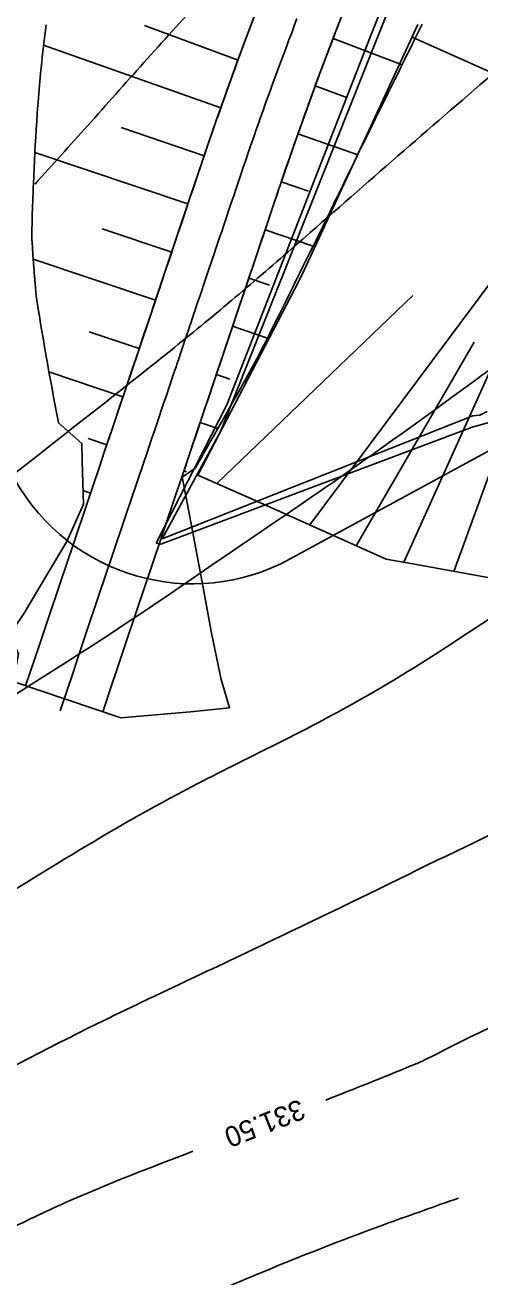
# Model space of a CAD drawing. Extents: x -564037 to -563827, y -1163561 to -1163412.
# Drawn here: x -563903.66 to -563892.49, y -1163523.9 to -1163493.12 of the extents above; entities that cross this region are included whole.
import ezdxf

# ---------------------------------------------------------------- set-up
doc = ezdxf.new("R2010")
doc.units = 0
for name, color, linetype in [('5', 7, 'Continuous'), ('Default', 7, 'Continuous'), ('Line', 7, 'Continuous'), ('Vrstva 24', 7, 'Continuous'), ('Vrstva 25', 7, 'Continuous'), ('Vrstva 26', 7, 'Continuous')]:
    doc.layers.add(name, color=color, linetype=linetype)

msp = doc.modelspace()

# ---------------------------------------------------------------- linework, layer by layer
for p, q in [((-563890.151, -1163481.173), (-563898.85, -1163503.099)), ((-563898.85, -1163503.099), (-563900.295, -1163505.749))]:
    msp.add_line(p, q)
msp.add_lwpolyline([(-563900.324, -1163505.882), (-563892.678, -1163503.006), (-563888.735, -1163501.906), (-563886.271, -1163502.018), (-563883.536, -1163500.684), (-563878.095, -1163497.234), (-563876.621, -1163489.849), (-563880.163, -1163485.998), (-563881.977, -1163484.515), (-563883.765, -1163483.269), (-563890.133, -1163481.092), (-563891.974, -1163485.382), (-563895.143, -1163493.304), (-563898.704, -1163502.458), (-563900.439, -1163505.855)], close=True)
for points in [[(-563901.709, -1163503.594), (-563901.519, -1163503.03), (-563901.312, -1163502.416), (-563901.2, -1163502.083), (-563900.88, -1163501.135), (-563900.561, -1163500.187), (-563900.242, -1163499.24), (-563899.923, -1163498.292), (-563899.604, -1163497.344), (-563899.329, -1163496.528), (-563899.284, -1163496.395), (-563898.956, -1163495.44), (-563898.618, -1163494.488), (-563898.566, -1163494.344), (-563898.27, -1163493.54), (-563897.913, -1163492.595)], [(-563899.813, -1163504.233), (-563899.623, -1163503.669), (-563899.417, -1163503.055), (-563899.304, -1163502.721), (-563898.985, -1163501.773), (-563898.666, -1163500.826), (-563898.347, -1163499.878), (-563898.027, -1163498.93), (-563897.708, -1163497.982), (-563897.433, -1163497.166), (-563897.39, -1163497.036), (-563897.068, -1163496.1), (-563896.736, -1163495.167), (-563896.685, -1163495.026), (-563896.396, -1163494.237), (-563896.046, -1163493.311), (-563895.888, -1163492.903)], [(-563903.651, -1163509.364), (-563903.434, -1163508.717), (-563903.304, -1163508.333), (-563903.114, -1163507.769), (-563902.795, -1163506.821), (-563902.476, -1163505.873), (-563902.157, -1163504.926), (-563901.838, -1163503.978), (-563901.709, -1163503.594), (-563901.613, -1163503.31), (-563901.612, -1163503.306), (-563901.552, -1163503.131), (-563901.519, -1163503.03), (-563901.493, -1163502.955), (-563901.434, -1163502.78), (-563901.375, -1163502.605), (-563901.316, -1163502.429), (-563901.257, -1163502.254), (-563901.2, -1163502.083), (-563901.198, -1163502.079), (-563901.139, -1163501.904), (-563901.08, -1163501.728), (-563901.021, -1163501.553), (-563900.962, -1163501.378), (-563900.903, -1163501.202), (-563900.88, -1163501.135), (-563900.844, -1163501.027), (-563900.785, -1163500.852), (-563900.726, -1163500.676), (-563900.667, -1163500.501), (-563900.608, -1163500.326), (-563900.561, -1163500.187), (-563900.549, -1163500.15), (-563900.49, -1163499.975), (-563900.431, -1163499.8), (-563900.372, -1163499.624), (-563900.313, -1163499.449), (-563900.254, -1163499.274), (-563900.242, -1163499.24), (-563900.194, -1163499.098), (-563900.135, -1163498.923), (-563900.076, -1163498.748), (-563900.017, -1163498.572), (-563899.958, -1163498.397), (-563899.923, -1163498.292), (-563899.899, -1163498.222), (-563899.84, -1163498.046), (-563899.781, -1163497.871), (-563899.722, -1163497.696), (-563899.663, -1163497.52), (-563899.604, -1163497.345), (-563899.604, -1163497.344), (-563899.545, -1163497.17), (-563899.486, -1163496.994), (-563899.427, -1163496.819), (-563899.368, -1163496.644), (-563899.329, -1163496.528), (-563899.309, -1163496.468), (-563899.284, -1163496.395), (-563899.249, -1163496.291), (-563899.188, -1163496.114), (-563899.128, -1163495.937), (-563899.067, -1163495.761), (-563899.006, -1163495.584), (-563898.956, -1163495.44), (-563898.944, -1163495.408), (-563898.882, -1163495.231), (-563898.82, -1163495.055), (-563898.758, -1163494.879), (-563898.695, -1163494.703), (-563898.632, -1163494.527), (-563898.618, -1163494.488), (-563898.568, -1163494.351), (-563898.566, -1163494.344), (-563898.504, -1163494.176), (-563898.44, -1163494), (-563898.376, -1163493.825), (-563898.311, -1163493.65), (-563898.27, -1163493.54), (-563898.246, -1163493.475), (-563898.18, -1163493.3), (-563898.115, -1163493.125), (-563898.048, -1163492.95)], [(-563902.226, -1163504.902), (-563902.261, -1163503.836), (-563902.265, -1163503.407), (-563902.843, -1163502.896), (-563902.843, -1163502.891), (-563902.884, -1163502.682), (-563902.907, -1163502.563), (-563902.924, -1163502.474), (-563902.964, -1163502.265), (-563903.002, -1163502.057), (-563903.041, -1163501.849), (-563903.078, -1163501.641), (-563903.115, -1163501.438), (-563903.115, -1163501.433), (-563903.152, -1163501.226), (-563903.188, -1163501.018), (-563903.223, -1163500.811), (-563903.258, -1163500.604), (-563903.292, -1163500.398), (-563903.305, -1163500.318), (-563903.326, -1163500.191), (-563903.359, -1163499.985), (-563903.391, -1163499.779), (-563903.411, -1163499.577), (-563903.427, -1163499.376), (-563903.439, -1163499.218), (-563903.442, -1163499.176), (-563903.457, -1163498.976), (-563903.471, -1163498.776), (-563903.485, -1163498.576), (-563903.498, -1163498.376), (-563903.499, -1163498.181), (-563903.498, -1163498.143), (-563903.493, -1163497.987), (-563903.488, -1163497.794), (-563903.482, -1163497.601), (-563903.475, -1163497.408), (-563903.468, -1163497.215), (-563903.463, -1163497.1), (-563903.46, -1163497.023), (-563903.451, -1163496.83), (-563903.442, -1163496.638), (-563903.433, -1163496.446), (-563903.423, -1163496.254), (-563903.413, -1163496.062), (-563903.413, -1163496.061), (-563903.402, -1163495.871), (-563903.39, -1163495.68), (-563903.378, -1163495.489), (-563903.365, -1163495.298), (-563903.357, -1163495.171), (-563903.352, -1163495.104), (-563903.345, -1163495.021), (-563903.336, -1163494.903), (-563903.319, -1163494.703), (-563903.302, -1163494.503), (-563903.283, -1163494.303), (-563903.263, -1163494.103), (-563903.246, -1163493.94), (-563903.242, -1163493.904), (-563903.221, -1163493.704), (-563903.198, -1163493.505), (-563903.174, -1163493.306), (-563903.149, -1163493.108)], [(-563902.805, -1163509.983), (-563902.486, -1163509.036), (-563902.357, -1163508.652), (-563902.167, -1163508.088), (-563901.848, -1163507.14), (-563901.528, -1163506.193), (-563901.209, -1163505.245), (-563900.89, -1163504.297), (-563900.761, -1163503.913), (-563900.665, -1163503.629), (-563900.664, -1163503.625), (-563900.605, -1163503.45), (-563900.571, -1163503.349), (-563900.546, -1163503.275), (-563900.487, -1163503.099), (-563900.428, -1163502.924), (-563900.369, -1163502.749), (-563900.31, -1163502.573), (-563900.252, -1163502.402), (-563900.251, -1163502.398), (-563900.191, -1163502.223), (-563900.132, -1163502.047), (-563900.073, -1163501.872), (-563900.014, -1163501.697), (-563899.955, -1163501.521), (-563899.933, -1163501.454), (-563899.896, -1163501.346), (-563899.837, -1163501.171), (-563899.778, -1163500.995), (-563899.719, -1163500.82), (-563899.66, -1163500.645), (-563899.613, -1163500.506), (-563899.601, -1163500.469), (-563899.542, -1163500.294), (-563899.483, -1163500.119), (-563899.424, -1163499.943), (-563899.365, -1163499.768), (-563899.306, -1163499.593), (-563899.294, -1163499.559), (-563899.247, -1163499.417), (-563899.188, -1163499.242), (-563899.129, -1163499.067), (-563899.07, -1163498.891), (-563899.011, -1163498.716), (-563898.975, -1163498.611), (-563898.952, -1163498.541), (-563898.893, -1163498.366), (-563898.833, -1163498.19), (-563898.774, -1163498.015), (-563898.715, -1163497.84), (-563898.656, -1163497.664), (-563898.656, -1163497.663), (-563898.597, -1163497.489), (-563898.538, -1163497.314), (-563898.479, -1163497.138), (-563898.42, -1163496.963), (-563898.381, -1163496.847), (-563898.361, -1163496.788), (-563898.337, -1163496.716), (-563898.302, -1163496.612), (-563898.242, -1163496.437), (-563898.182, -1163496.262), (-563898.122, -1163496.087), (-563898.061, -1163495.913), (-563898.012, -1163495.77), (-563898, -1163495.738), (-563897.939, -1163495.563), (-563897.878, -1163495.389), (-563897.816, -1163495.215), (-563897.753, -1163495.04), (-563897.691, -1163494.866), (-563897.677, -1163494.828), (-563897.628, -1163494.692), (-563897.625, -1163494.685), (-563897.565, -1163494.518), (-563897.501, -1163494.345), (-563897.437, -1163494.171), (-563897.373, -1163493.997), (-563897.333, -1163493.889), (-563897.309, -1163493.824), (-563897.244, -1163493.651), (-563897.179, -1163493.478), (-563897.113, -1163493.305), (-563897.048, -1163493.132), (-563896.982, -1163492.959)], [(-563901.756, -1163510.002), (-563901.538, -1163509.355), (-563901.409, -1163508.971), (-563901.219, -1163508.407), (-563900.9, -1163507.459), (-563900.581, -1163506.512), (-563900.262, -1163505.564), (-563899.942, -1163504.616), (-563899.813, -1163504.233), (-563899.717, -1163503.948), (-563899.716, -1163503.944), (-563899.657, -1163503.769), (-563899.623, -1163503.669), (-563899.598, -1163503.594), (-563899.539, -1163503.418), (-563899.48, -1163503.243), (-563899.421, -1163503.068), (-563899.362, -1163502.892), (-563899.304, -1163502.721), (-563899.303, -1163502.717), (-563899.244, -1163502.542), (-563899.185, -1163502.367), (-563899.126, -1163502.191), (-563899.067, -1163502.016), (-563899.008, -1163501.841), (-563898.985, -1163501.773), (-563898.949, -1163501.665), (-563898.89, -1163501.49), (-563898.83, -1163501.315), (-563898.771, -1163501.139), (-563898.712, -1163500.964), (-563898.666, -1163500.826), (-563898.653, -1163500.789), (-563898.594, -1163500.613), (-563898.535, -1163500.438), (-563898.476, -1163500.263), (-563898.417, -1163500.087), (-563898.358, -1163499.912), (-563898.347, -1163499.878), (-563898.299, -1163499.737), (-563898.24, -1163499.561), (-563898.181, -1163499.386), (-563898.122, -1163499.211), (-563898.063, -1163499.035), (-563898.027, -1163498.93), (-563898.004, -1163498.86), (-563897.945, -1163498.685), (-563897.886, -1163498.509), (-563897.827, -1163498.334), (-563897.768, -1163498.159), (-563897.709, -1163497.983), (-563897.708, -1163497.982), (-563897.65, -1163497.808), (-563897.591, -1163497.633), (-563897.532, -1163497.457), (-563897.472, -1163497.282), (-563897.433, -1163497.166), (-563897.414, -1163497.107), (-563897.39, -1163497.036), (-563897.355, -1163496.934), (-563897.296, -1163496.76), (-563897.236, -1163496.587), (-563897.177, -1163496.414), (-563897.117, -1163496.241), (-563897.068, -1163496.1), (-563897.056, -1163496.068), (-563896.996, -1163495.895), (-563896.935, -1163495.723), (-563896.874, -1163495.55), (-563896.812, -1163495.378), (-563896.75, -1163495.205), (-563896.736, -1163495.167), (-563896.688, -1163495.033), (-563896.685, -1163495.026), (-563896.625, -1163494.861), (-563896.562, -1163494.689), (-563896.499, -1163494.517), (-563896.436, -1163494.345), (-563896.396, -1163494.237), (-563896.372, -1163494.173), (-563896.308, -1163494.002), (-563896.243, -1163493.83), (-563896.178, -1163493.659), (-563896.113, -1163493.488), (-563896.048, -1163493.317), (-563896.046, -1163493.311), (-563895.982, -1163493.146), (-563895.916, -1163492.975)], [(-563899.803, -1163504.236), (-563899.49, -1163504.025), (-563899.488, -1163504.021), (-563899.394, -1163503.858), (-563899.34, -1163503.764), (-563899.3, -1163503.694), (-563899.206, -1163503.531), (-563899.113, -1163503.367), (-563899.019, -1163503.203), (-563898.926, -1163503.039), (-563898.835, -1163502.879), (-563898.833, -1163502.875), (-563898.74, -1163502.711), (-563898.648, -1163502.547), (-563898.555, -1163502.383), (-563898.463, -1163502.219), (-563898.371, -1163502.055), (-563898.336, -1163501.992), (-563898.28, -1163501.89), (-563898.19, -1163501.725), (-563898.1, -1163501.561), (-563898.01, -1163501.396), (-563897.92, -1163501.231), (-563897.853, -1163501.099), (-563897.835, -1163501.064), (-563897.75, -1163500.897), (-563897.666, -1163500.731), (-563897.582, -1163500.564), (-563897.499, -1163500.397), (-563897.415, -1163500.23), (-563897.399, -1163500.197), (-563897.332, -1163500.062), (-563897.249, -1163499.895), (-563897.166, -1163499.728), (-563897.083, -1163499.561), (-563897, -1163499.393), (-563896.951, -1163499.293), (-563896.918, -1163499.226), (-563896.836, -1163499.058), (-563896.754, -1163498.891), (-563896.671, -1163498.723), (-563896.588, -1163498.556), (-563896.506, -1163498.388), (-563896.505, -1163498.388), (-563896.424, -1163498.221), (-563896.342, -1163498.053), (-563896.26, -1163497.886), (-563896.178, -1163497.718), (-563896.124, -1163497.607), (-563896.097, -1163497.552), (-563896.065, -1163497.484), (-563896.018, -1163497.388), (-563895.938, -1163497.224), (-563895.858, -1163497.061), (-563895.779, -1163496.897), (-563895.699, -1163496.734), (-563895.634, -1163496.601), (-563895.619, -1163496.571), (-563895.54, -1163496.408), (-563895.46, -1163496.245), (-563895.38, -1163496.082), (-563895.3, -1163495.919), (-563895.22, -1163495.756), (-563895.202, -1163495.72), (-563895.14, -1163495.594), (-563895.137, -1163495.587), (-563895.06, -1163495.431), (-563894.98, -1163495.269), (-563894.9, -1163495.106), (-563894.82, -1163494.944), (-563894.77, -1163494.842), (-563894.74, -1163494.782), (-563894.66, -1163494.62), (-563894.58, -1163494.458), (-563894.5, -1163494.296), (-563894.42, -1163494.134), (-563894.339, -1163493.972), (-563894.337, -1163493.967), (-563894.259, -1163493.81), (-563894.179, -1163493.649), (-563894.145, -1163493.581), (-563894.099, -1163493.487), (-563894.019, -1163493.325), (-563893.939, -1163493.164), (-563893.904, -1163493.093)], [(-563900.295, -1163505.749), (-563892.658, -1163502.726), (-563892.5, -1163502.714), (-563892.491, -1163502.712), (-563892.306, -1163502.622)], [(-563901.311, -1163510.152), (-563899.601, -1163510.007), (-563898.639, -1163509.904), (-563898.845, -1163509.207), (-563899.079, -1163508.073), (-563899.291, -1163506.946), (-563899.504, -1163505.819), (-563899.717, -1163504.692), (-563899.803, -1163504.236)], [(-563901.311, -1163510.152), (-563903.956, -1163509.261), (-563903.825, -1163508.585), (-563904.027, -1163508.089), (-563903.682, -1163507.578), (-563903.161, -1163506.698), (-563902.64, -1163505.818), (-563902.226, -1163504.902)]]:
    msp.add_lwpolyline(points)
at = {"layer": '5'}
msp.add_line((-563897.15, -1163506.247), (-563862.812, -1163487.513), dxfattribs=at)
msp.add_arc((-563899.545, -1163501.858), 5, 209.1194, 298.6163, dxfattribs=at)
at = {"layer": 'Default'}
msp.add_lwpolyline([(-563894.011, -1163493.107), (-563894.298, -1163493.726), (-563896.807, -1163499.145), (-563896.925, -1163499.399), (-563897.869, -1163501.213), (-563898.286, -1163502.014), (-563899.415, -1163504.184), (-563898.029, -1163504.804), (-563894.792, -1163506.25), (-563894.189, -1163506.359), (-563890.445, -1163507.038), (-563890.304, -1163507.064), (-563887.435, -1163506.214), (-563885.296, -1163505.58), (-563883.769, -1163504.643), (-563881.393, -1163503.187), (-563879.621, -1163502.1), (-563877.447, -1163498.123), (-563877.26, -1163497.64), (-563876.56, -1163495.83), (-563876.213, -1163494.931), (-563876.002, -1163494.387), (-563875.979, -1163493.391), (-563875.957, -1163492.484)], dxfattribs=at)
at = {"layer": 'Line'}
for p, q in [((-563900.732, -1163493.131), (-563898.43, -1163493.976)), ((-563896.095, -1163493.444), (-563894.399, -1163494.092)), ((-563894.152, -1163493.411), (-563889.486, -1163495.501)), ((-563898.853, -1163495.152), (-563903.21, -1163493.612)), ((-563895.74, -1163494.906), (-563896.534, -1163494.614)), ((-563901.301, -1163495.636), (-563899.263, -1163496.333)), ((-563896.958, -1163495.79), (-563895.491, -1163496.309)), ((-563896.67, -1163505.411), (-563889.53, -1163495.82)), ((-563894.356, -1163506.329), (-563889.596, -1163495.749)), ((-563899.662, -1163497.517), (-563903.423, -1163496.25)), ((-563896.702, -1163497.198), (-563897.367, -1163496.971)), ((-563901.77, -1163498.126), (-563900.061, -1163498.702)), ((-563897.767, -1163498.156), (-563896.587, -1163498.553)), ((-563900.46, -1163499.886), (-563903.464, -1163498.875)), ((-563897.655, -1163499.512), (-563898.166, -1163499.34)), ((-563898.953, -1163504.391), (-563894.136, -1163499.765)), ((-563898.565, -1163500.525), (-563897.708, -1163500.813)), ((-563902.088, -1163500.657), (-563900.859, -1163501.071)), ((-563892.627, -1163500.918), (-563895.529, -1163505.921)), ((-563891.196, -1163501.236), (-563893.126, -1163506.552)), ((-563901.258, -1163502.256), (-563903.078, -1163501.643)), ((-563898.633, -1163501.821), (-563898.963, -1163501.709)), ((-563899.362, -1163502.894), (-563898.927, -1163503.041)), ((-563902.117, -1163503.285), (-563901.657, -1163503.44)), ((-563899.698, -1163504.1), (-563899.761, -1163504.079)), ((-563902.056, -1163504.625), (-563902.237, -1163504.564))]:
    msp.add_line(p, q, dxfattribs=at)
at = {"layer": 'Vrstva 24'}
for points in [[(-563903.419, -1163497.029), (-563902.125, -1163495.59), (-563900.744, -1163494.039), (-563899.345, -1163492.505), (-563898.448, -1163491.553), (-563897.897, -1163490.941), (-563897.635, -1163490.622), (-563897.383, -1163490.29), (-563897.001, -1163489.401), (-563896.398, -1163486.71), (-563896.305, -1163486.212), (-563896.276, -1163485.962), (-563896.268, -1163485.713), (-563896.394, -1163485.294), (-563896.666, -1163484.924), (-563897.969, -1163483.548), (-563899.309, -1163482.237), (-563900.743, -1163480.898), (-563903.659, -1163478.289), (-563907.403, -1163474.951), (-563909.511, -1163473.024), (-563914.099, -1163468.742), (-563916.271, -1163466.637)], [(-563905.221, -1163519.388), (-563901.417, -1163517.444), (-563900.291, -1163516.907), (-563895.909, -1163514.815), (-563892.135, -1163512.984), (-563890.63, -1163512.267), (-563888.864, -1163511.357), (-563887.99, -1163510.869), (-563887.125, -1163510.367), (-563886.26, -1163509.866), (-563885.383, -1163509.384), (-563882.362, -1163507.826), (-563880.585, -1163506.938), (-563878.549, -1163505.818), (-563872.848, -1163502.599), (-563870.632, -1163501.288), (-563869.542, -1163500.601), (-563868.575, -1163499.969)], [(-563931.161, -1163537.124), (-563928.768, -1163536.86), (-563922.688, -1163536.158), (-563922.482, -1163536.112), (-563922.145, -1163535.991), (-563913.265, -1163532.02), (-563912.083, -1163531.357), (-563910.91, -1163530.589), (-563907.314, -1163528.363), (-563903.77, -1163526.446), (-563900.567, -1163524.953), (-563899.119, -1163524.329), (-563897.667, -1163523.716), (-563894.732, -1163522.576), (-563893.017, -1163521.965)]]:
    msp.add_spline(points, degree=3, dxfattribs=at)
at = {"layer": 'Vrstva 25'}
msp.add_spline([(-563905.141, -1163510.37), (-563904.922, -1163510.229), (-563901.706, -1163508.177), (-563898.297, -1163505.868), (-563895.6, -1163504.013), (-563893.249, -1163502.324), (-563892.081, -1163501.469), (-563890.919, -1163500.608), (-563889.757, -1163499.746), (-563888.589, -1163498.892), (-563887.491, -1163498.145), (-563886.364, -1163497.441), (-563885.229, -1163496.747), (-563884.107, -1163496.03), (-563883.48, -1163495.59), (-563883.181, -1163495.349), (-563882.893, -1163495.092), (-563882.209, -1163494.336), (-563881.626, -1163493.502), (-563881.193, -1163492.783), (-563880.36, -1163491.213), (-563880.004, -1163490.417), (-563879.711, -1163489.616), (-563879.829, -1163489.186), (-563884.789, -1163483.345)], degree=3, dxfattribs=at)
at = {"layer": 'Vrstva 26'}
for points in [[(-563904.255, -1163504.408), (-563901.932, -1163502.584), (-563900.774, -1163501.667), (-563899.621, -1163500.744), (-563898.128, -1163499.495), (-563896.658, -1163498.219), (-563892.051, -1163494.217), (-563891.058, -1163493.351), (-563890.3, -1163492.602), (-563889.946, -1163492.201), (-563889.6, -1163491.789), (-563889.274, -1163491.333), (-563889.128, -1163491.092), (-563888.986, -1163490.845), (-563888.757, -1163490.393), (-563888.565, -1163489.929), (-563888.402, -1163489.454), (-563888.258, -1163488.97), (-563888.179, -1163488.634), (-563888.132, -1163488.29), (-563888.126, -1163487.946), (-563888.168, -1163487.609), (-563888.372, -1163487.087), (-563888.888, -1163486.275), (-563889.418, -1163485.493), (-563889.974, -1163484.737), (-563890.569, -1163484.004), (-563892.45, -1163481.915), (-563894.839, -1163479.601), (-563896.896, -1163477.665), (-563897.939, -1163476.713), (-563899, -1163475.779), (-563899.292, -1163475.563), (-563900.233, -1163474.949)], [(-563906.28, -1163515.803), (-563905.884, -1163515.571), (-563902.883, -1163513.741), (-563899.929, -1163512.038), (-563897.928, -1163511.018), (-563895.553, -1163509.778), (-563893.055, -1163508.246), (-563892.353, -1163507.782), (-563891.657, -1163507.311), (-563890.96, -1163506.841), (-563890.257, -1163506.379), (-563888.16, -1163505.094), (-563886.21, -1163504.031), (-563880.965, -1163501.085), (-563878.454, -1163499.578), (-563877.23, -1163498.772), (-563876.032, -1163497.922), (-563874.901, -1163496.941), (-563873.614, -1163495.651), (-563873.276, -1163495.107), (-563873.154, -1163494.587), (-563873.048, -1163494.066), (-563872.865, -1163493.019), (-563872.827, -1163492.778)], [(-563896.274, -1163519.554), (-563894.165, -1163518.707), (-563893.901, -1163518.593), (-563893.686, -1163518.487), (-563888.411, -1163515.922), (-563883.796, -1163513.845), (-563882.856, -1163513.463), (-563881.551, -1163512.898), (-563877.829, -1163511.052), (-563874.459, -1163509.5), (-563873.358, -1163509.055), (-563872.244, -1163508.643), (-563871.128, -1163508.237), (-563870.019, -1163507.811), (-563865.656, -1163505.903), (-563863.431, -1163504.67), (-563862.373, -1163503.951), (-563861.332, -1163503.174), (-563860.403, -1163502.078), (-563859.968, -1163500.761)], [(-563938.247, -1163534.094), (-563936.943, -1163534.069), (-563931.73, -1163533.621), (-563930.272, -1163533.423), (-563929.328, -1163533.288), (-563925.493, -1163532.585), (-563923.592, -1163532.141), (-563921.698, -1163531.646), (-563918.724, -1163530.654), (-563917.276, -1163530.052), (-563915.858, -1163529.378), (-563913.985, -1163528.389), (-563912.146, -1163527.347), (-563909.112, -1163525.55), (-563905.848, -1163523.712), (-563904.199, -1163522.809), (-563902.671, -1163522.075), (-563899.54, -1163520.813)]]:
    msp.add_spline(points, degree=3, dxfattribs=at)

# ---------------------------------------------------------------- texts
at = {"layer": 'Vrstva 25'}
msp.add_text('331.50', height=0.5, rotation=201.5654, dxfattribs=at).set_placement((-563896.912, -1163519.52))

doc.saveas('drawing.dxf')
